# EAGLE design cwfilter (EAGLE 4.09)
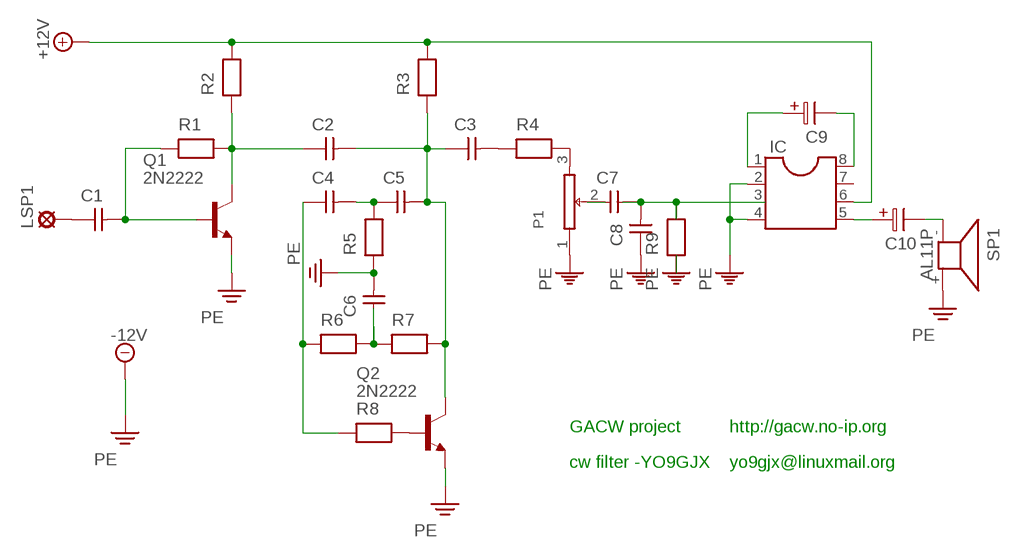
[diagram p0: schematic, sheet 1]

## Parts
C1  CAPNP-5  [C-5]
C2  CAPNP-5  [C-5]
C3  CAPNP-5  [C-5]
C4  CAPNP-5  [C-5]
C5  CAPNP-5  [C-5]
C6  CAPNP-5  [C-5]
C7  CAPNP-5  [C-5]
C8  CAPNP-5  [C-5]
C9  ELC-2,5  [ES-2,5]
C10  ELC-2,5  [ES-2,5]
IC  DIL8  [DIL08]
LSP1  LSP10  [LSP10]
P1  POTF_1  [POTF_1]
Q1  2N2222  [TO18]
Q2  2N2222  [TO18]
R1  RESEU-5  [R-5]
R2  RESEU-5  [R-5]
R3  RESEU-5  [R-5]
R4  RESEU-5  [R-5]
R5  RESEU-5  [R-5]
R6  RESEU-5  [R-5]
R7  RESEU-5  [R-5]
R8  RESEU-5  [R-5]
R9  RESEU-5  [R-5]
SP1  AL11P  [AL11P]

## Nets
+12V: IC.6 R2.2 R3.2
IC: C7.2 C8.2 R9.2
LM386: C10.1 IC.5
N$1: C2.1 Q1.3(C) R1.2 R2.1
N$2: C1.2 Q1.2(B) R1.1
N$3: C2.2 C3.1 C5.2 Q2.3(C) R3.1 R7.2
N$4: C3.2 R4.1
N$5: P1.3 R4.2
N$6: C1.1 LSP1.MP
N$7: Q2.2(B) R8.2
N$8: C4.2 C5.1 R5.2
N$9: C7.1 P1.2
N$10: C9.1 IC.1
N$11: C6.1 R6.2 R7.1
N$12: C4.1 R6.1 R8.1
N$13: C9.2 IC.8
N$17: C10.2 SP1.-
PE: C6.2 C8.1 IC.2 IC.4 P1.1 Q1.1(E) Q2.1(E) R5.1 R9.1 SP1.+ ; supply symbol labelled -12V
Unconnected: IC.3 IC.7

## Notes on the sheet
- GACW project | http://gacw.no-ip.org
- cw filter -YO9GJX | yo9gjx@linuxmail.org

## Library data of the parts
C1-C8 = discrete:CAPNP-5
C9 C10 = discrete:ELC-2,5
IC = dil:DIL8: SOCKET Dual In Line
LSP1 = solpad:LSP10: SOLDER PAD
P1 = Pot:POTF_1
Q1 Q2 = transistor-npn:2N2222*: NPN Transistor
R1-R9 = discrete:RESEU-5
SP1 = buzzer:AL11P: SPEAKER

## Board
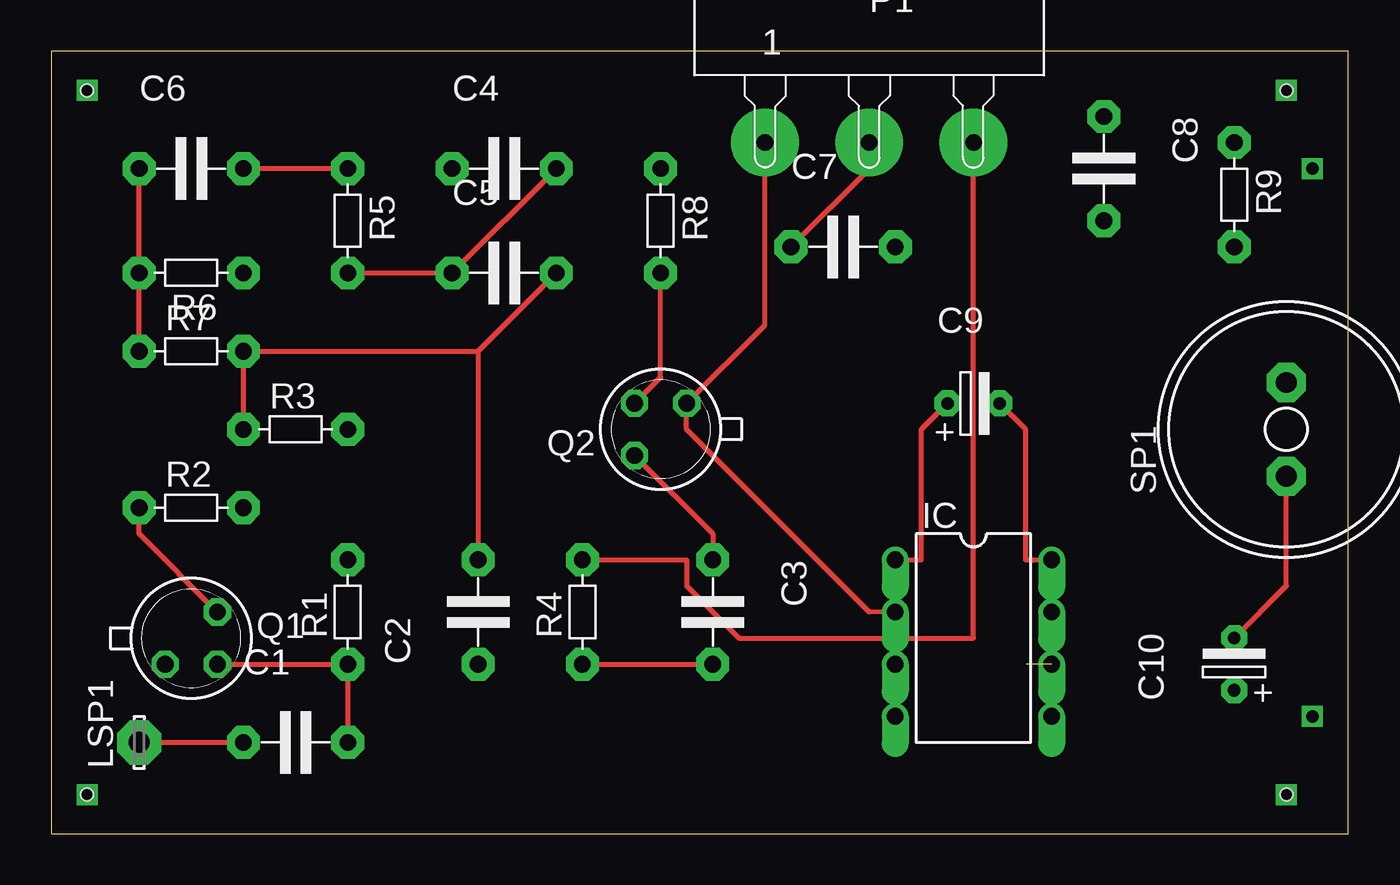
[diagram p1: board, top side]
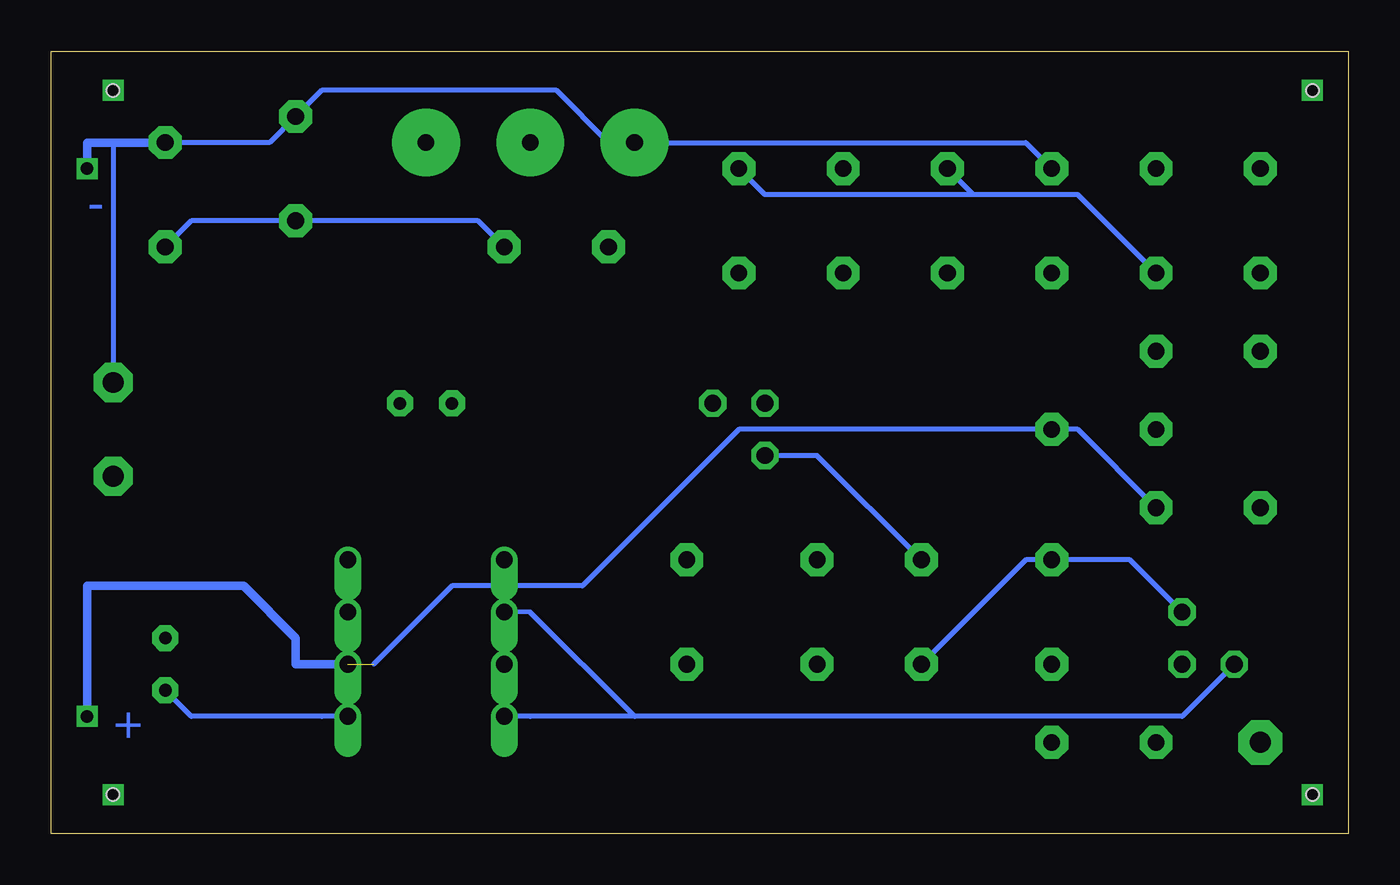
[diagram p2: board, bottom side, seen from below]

Size 63.17 x 38.09 mm. Coordinates in mm from the lower left corner, seen from the top.
Outline: 0,0 63.17,0 63.17,38.09 0,38.09 0,0
Copper layers used: Top, Bottom
Holes 0.61 mm at 1.74,36.19 1.74,1.9 60.16,1.9 60.16,36.19

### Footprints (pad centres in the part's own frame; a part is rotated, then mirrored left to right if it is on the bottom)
C-5 = drill 0.813 pad 1.6 octagon: 1 -2.54,0; 2 2.54,0
ES-2,5 = drill 0.61 pad 1.27 octagon: 1 -1.27,0; 2 1.27,0
DIL08 = drill 0.813 offset: 1 -3.81,-3.81; 2 -1.27,-3.81; 3 1.27,-3.81; 4 3.81,-3.81; 5 3.81,3.81; 6 1.27,3.81; 7 -1.27,3.81; 8 -3.81,3.81
LSP10 = drill 1.016 pad 2.159 octagon: MP 0,0
POTF_1 = drill 0.813 pad 3.302 round: 1 -5.08,-17.78; 2 0,-17.78; 3 5.08,-17.78
TO18 = drill 0.813 octagon: 1 -1.27,-1.27; 2 1.27,-1.27; 3 1.27,1.27
R-5 = drill 0.813 pad 1.6 octagon: 1 -2.54,0; 2 2.54,0
AL11P = drill 1.016 pad 1.905 octagon: + 2.286,0; - -2.286,0

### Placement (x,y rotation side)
C1  11.9,4.44 0 top
C2  20.79,10.79 90 top
C3  32.22,10.79 270 top
C4  22.06,32.38 0 top
C5  22.06,27.3 0 top
C6  6.82,32.38 0 top
C7  38.57,28.57 0 top
C8  51.27,32.38 270 top
C9  44.92,20.95 0 top
C10  57.62,8.25 90 top
IC  44.92,9.52 270 top
LSP1  4.28,4.44 90 top
P1  39.84,51.43 0 top
Q1  6.82,9.52 0 top
Q2  29.68,19.68 180 top
R1  14.44,10.79 90 top
R2  6.82,15.87 0 top
R3  11.9,19.68 0 top
R4  25.87,10.79 90 top
R5  14.44,29.84 270 top
R6  6.82,27.3 180 top
R7  6.82,23.49 0 top
R8  29.68,29.84 270 top
R9  57.62,31.11 270 top
SP1  60.16,19.68 90 top

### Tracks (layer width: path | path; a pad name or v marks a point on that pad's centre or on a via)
+12V  (via drill 0.61)  (1 unrouted)
  Bottom 0.254: 47.46,8.25 43.65,12.06 37.3,12.06 29.68,19.68 R3.2 | R2.2 13.17,19.68 R3.2 | R2.2 | R3.2
  Bottom 0.406: IC.6 51.27,8.25 51.27,9.52 53.81,12.06 61.43,12.06 v61.43,5.71
IC
  Bottom 0.254: C7.2 42.38,29.84 C8.2 | C7.2 | R9.2 56.35,29.84 C8.2 | R9.2 | C8.2
LM386
  Bottom 0.254: C10.1 56.35,5.71 50,5.71 IC.5 | C10.1
N$1
  Top 0.254: Q1.3 4.28,14.6 R2.1 | Q1.3
  Bottom 0.254: C2.1 15.71,13.33 R1.2 | C2.1 | Q1.3 10.63,13.33 R1.2 | Q1.3 | R1.2
N$2
  Top 0.254: Q1.2 R1.1 | Q1.2 | R1.1 C1.2 | C1.2 | R1.1
N$3
  Top 0.254: R3.1 R7.2 | R3.1 | Q2.3 32.22,14.6 C3.1 | Q2.3 | C3.1 | 20.79,23.49 C5.2 | 20.79,23.49 C2.2 | C5.2 | C2.2 | R7.2 20.79,23.49 | R7.2
  Bottom 0.254: C2.2 25.87,18.41 Q2.3 | C2.2 | Q2.3
N$4
  Top 0.254: R4.1 C3.2 | R4.1 | C3.2
N$5
  Top 0.254: R4.2 30.95,13.33 30.95,12.06 33.49,9.52 44.92,9.52 P1.3 | R4.2
N$6
  Top 0.254: LSP1.MP C1.1 | C1.1 | LSP1.MP
N$7
  Top 0.254: Q2.2 29.68,22.22 R8.2 | Q2.2
N$8
  Top 0.254: R5.2 C5.1 | R5.2 | C5.1 C4.2 | C4.2 | C5.1
N$9
  Top 0.254: C7.1 39.84,32.38 P1.2 | C7.1
N$10
  Top 0.254: C9.1 42.38,19.68 42.38,13.33 IC.1 | C9.1
N$11
  Top 0.254: R7.1 R6.2 | R7.1 | R6.2 C6.1 | R6.2
N$12
  Bottom 0.254: R6.1 13.17,31.11 18.25,31.11 | 18.25,31.11 C4.1 | R6.1 | C4.1 | R8.1 28.41,31.11 18.25,31.11 | R8.1
N$13
  Top 0.254: C9.2 47.46,19.68 47.46,13.33 IC.8 | C9.2
N$14  (via drill 0.61)
  other vias: 1.74,36.19
N$15  (via drill 0.61)
  other vias: 1.74,1.9
N$16  (via drill 0.61)
  other vias: 60.16,1.9
N$17
  Top 0.254: C10.2 60.16,12.06 SP1.- | C10.2
N$18  (via drill 0.61)
  other vias: 60.16,36.19
PE  (via drill 0.61)
  Top 0.254: R5.1 C6.2 | C6.2 | R5.1 | Q2.1 34.76,24.76 P1.1 | Q2.1 30.95,19.68 39.84,10.79 IC.2 | Q2.1
  Bottom 0.254: Q1.1 8.09,5.71 34.76,5.71 | 34.76,5.71 39.84,5.71 IC.4 | Q1.1 | 34.76,5.71 39.84,10.79 IC.2 | C8.1 52.54,33.65 R9.1 | 60.16,33.65 SP1.+ | R5.1 15.71,33.65 33.49,33.65 P1.1 36.03,33.65 38.57,36.19 50,36.19 C8.1 | R5.1 | C8.1
  Bottom 0.406: 61.43,33.65 60.16,33.65 | 61.43,33.65 | 61.43,33.65 v61.43,32.38 61.43,33.65 | R9.1 | R9.1 61.43,33.65

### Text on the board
Bottom: - | +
